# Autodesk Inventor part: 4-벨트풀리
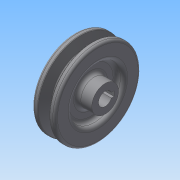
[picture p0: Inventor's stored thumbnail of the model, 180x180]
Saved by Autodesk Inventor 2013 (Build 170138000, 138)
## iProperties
Created: 2015-02
Part Number: 4-벨트풀리
Material: 일반
Document SubType Name: Modeling
Designer: Administrator
Density: 1 g/cm^3
Author: Administrator
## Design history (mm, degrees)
sketch "스케치1"
  geometry: L1 (0, 0)-(25, 0); L2 (25, 0)-(25, 11); L3 (25, 11)-(13, 11); L4 (13, 11)-(13, 21.5); L5 (13, 21.5)-(19, 21.5); L6 (19, 21.5)-(19, 35.2); L7 (19, 35.2)-(14.325, 35.2); L8 (14.325, 35.2)-(11.574, 26.2); L9 (11.574, 26.2)-(7.426, 26.2); L10 (7.426, 26.2)-(4.675, 35.2); L11 (4.675, 35.2)-(0, 35.2); L12 (0, 35.2)-(0, 21.5); L13 (0, 21.5)-(6, 21.5); L14 (6, 21.5)-(6, 11); L15 (6, 11)-(0, 11); L16 (0, 11)-(0, 0); 2 further points
  constraints: 32 end point, 10 parallel, 5 collinear, 3 equal length, 2 perpendicular, 2 point on line, 1 horizontal, 1 horizontal alignment
  dimensions: "d0" = 25 distance of L1.start L1.end; "d1" = 22 diameter of L3 L1; "d2" = 43 diameter of L13 L1; "d3" = 6 distance of L4.end L5.end; "d4" = 2.7 vertical distance of L10.end point (5.5, 32.5); "d5" = 6.3 vertical distance of L9.end point (5.5, 32.5); "d7" = 8 distance of point (13.5, 32.5) point (5.5, 32.5); "d8" = 34 deg angle of L8 L10; "d9" = 65 diameter of point (5.5, 32.5) L1; "d10" = 19 distance between parallel lines of L6 L12
revolve "회전1" sketch "스케치1" stored, may be unused: angle "d11" = 90 deg
sketch "스케치2"
  geometry: L1 (2, 5.123)-(2, 7.3); L2 (2, 7.3)-(-2, 7.3); L3 (-2, 7.3)-(-2, 5.123); C1 r 11 at (0, 0) reference; A1 r 5.5 centre (0, 0) between (-2, 5.123) and (2, 5.123)
  constraints: 6 end point, 2 parallel, 2 point on circle, 1 centre point, 1 coincident, 1 perpendicular, 1 vertical
  dimensions: "d12" = 11 diameter of A1; "d14" = 4 distance of L1.end L2.end; "d15" = 12.8 dimension on A1 L2
extrude "돌출1" cut sketch "스케치2" stored distance "d16" = 10; taper "d17" = 0 deg
fillet "모깎기1" dims "d18" = 0.5, "d19" = 1, "d20" = 2, "d21" = 3
node "솔리드1"
